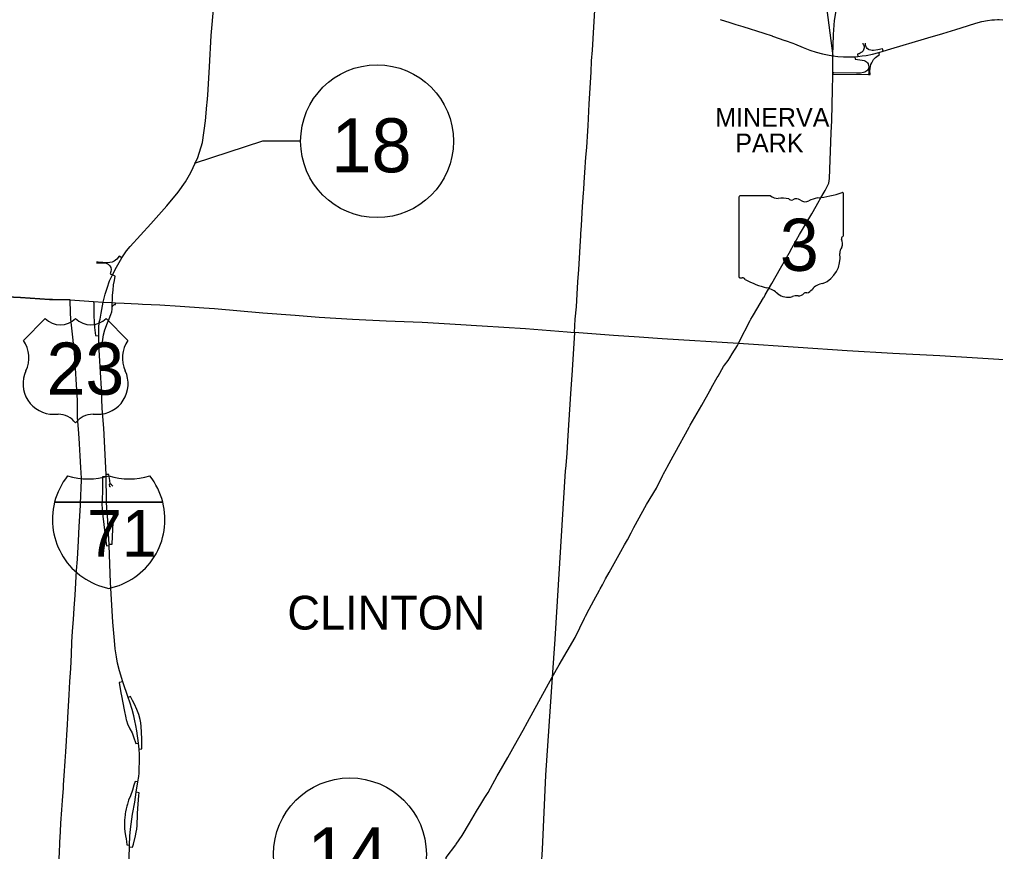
# Model space of a CAD drawing. Extents: x -1146 to -445, y -1283 to -822.
# Drawn here: x -887.8 to -822.8, y -1003.9 to -948.4 of the extents above; entities that cross this region are included whole.
import ezdxf

# ---------------------------------------------------------------- set-up
doc = ezdxf.new("R2010")
doc.units = 0
for name, color, linetype in [('Default', 7, 'Continuous'), ('GM_X_Corporation_Text', 7, 'Continuous'), ('GM_X_Interchange_Ramps', 7, 'Continuous'), ('GM_X_Interstate_Route', 7, 'Continuous'), ('GM_X_Interstate_Shield', 7, 'Continuous'), ('GM_X_State_Route', 7, 'Continuous'), ('GM_X_State_Shield', 7, 'Continuous'), ('GM_X_Township', 7, 'Continuous'), ('GM_X_Township_Text', 7, 'Continuous'), ('GM_X_US_Route', 7, 'Continuous'), ('GM_X_US_Shield', 7, 'Continuous')]:
    doc.layers.add(name, color=color, linetype=linetype)

msp = doc.modelspace()

# ---------------------------------------------------------------- linework, layer by layer
at = {"layer": 'Default'}
for points in [[(-837.735, -938.717), (-835.188, -938.717), (-833.622, -950.863)], [(-869.091, -956.557), (-871.638, -956.557), (-876.187, -958.029)]]:
    msp.add_lwpolyline(points, dxfattribs=at)
for centre in [(-863.997, -956.557), (-865.804, -1004.109)]:
    msp.add_circle(centre, 5.094, dxfattribs=at)
at = {"layer": 'GM_X_Interchange_Ramps'}
for points in [[(-831.618, -950.017), (-831.616, -950.063), (-831.572, -950.114), (-831.55, -950.171), (-831.538, -950.235), (-831.54, -950.318), (-831.552, -950.403), (-831.574, -950.468), (-831.603, -950.523), (-831.635, -950.561), (-831.678, -950.608), (-831.73, -950.646), (-831.792, -950.689), (-831.858, -950.72), (-831.911, -950.737), (-831.963, -950.745), (-831.957, -950.899)], [(-830.252, -950.545), (-830.296, -950.39), (-830.61, -950.45), (-830.905, -950.494), (-830.993, -950.498), (-831.082, -950.49), (-831.19, -950.468), (-831.247, -950.432), (-831.321, -950.379), (-831.377, -950.313), (-831.404, -950.26), (-831.442, -950.15), (-831.444, -950.07), (-831.447, -950.009)], [(-833.626, -952.081), (-833.56, -952.082), (-831.23, -952.113), (-831.139, -952.111), (-831.141, -951.85), (-831.135, -951.701), (-831.116, -951.574), (-831.076, -951.443), (-831.028, -951.323), (-830.956, -951.192), (-830.897, -951.11), (-830.847, -951.045), (-830.773, -950.971), (-830.686, -950.896), (-830.604, -950.83), (-830.513, -950.78), (-830.555, -950.63)], [(-832.141, -950.917), (-832.136, -951.081), (-831.659, -951.152), (-831.539, -951.18), (-831.45, -951.218), (-831.372, -951.266), (-831.31, -951.331), (-831.267, -951.401), (-831.235, -951.494), (-831.229, -951.602), (-831.249, -951.699), (-831.273, -951.745), (-831.306, -951.807), (-831.35, -951.86), (-831.408, -951.908), (-831.493, -951.954), (-831.573, -951.98), (-831.776, -952.01), (-832.033, -952.022), (-833.549, -951.993), (-833.626, -951.992)], [(-831.249, -951.699), (-831.219, -951.703), (-831.224, -952.039), (-831.23, -952.113)], [(-882.701, -964.661), (-882.603, -964.665), (-882.05, -964.693), (-881.909, -964.747), (-881.809, -964.866), (-881.751, -964.978), (-881.728, -965.113), (-881.748, -965.246), (-881.795, -965.395), (-881.637, -965.467)], [(-881.008, -964.337), (-881.174, -964.216), (-881.345, -964.417), (-881.513, -964.548), (-881.66, -964.624), (-881.809, -964.651), (-881.953, -964.659), (-882.592, -964.628), (-882.698, -964.622)], [(-881.653, -967.321), (-881.639, -967.181), (-881.622, -966.827), (-881.595, -966.497), (-881.555, -966.141), (-881.502, -965.842), (-881.442, -965.556), (-881.637, -965.467)], [(-882.885, -967.245), (-882.865, -967.388), (-882.877, -967.789), (-882.88, -968.19), (-882.854, -968.593), (-882.826, -968.967), (-882.764, -969.521), (-882.551, -969.525)], [(-882.532, -970.119), (-882.316, -970.107), (-882.282, -969.778), (-882.226, -969.47), (-882.135, -969.13), (-881.968, -968.668), (-881.856, -968.391), (-881.744, -968.118), (-881.684, -967.935), (-881.657, -967.764), (-881.649, -967.573), (-881.647, -967.406), (-881.653, -967.321)], [(-881.649, -967.573), (-881.632, -967.574), (-881.609, -967.519), (-881.571, -967.485), (-881.534, -967.462), (-881.489, -967.451), (-881.43, -967.444), (-881.434, -967.328)], [(-882.049, -978.937), (-882.299, -978.947), (-882.306, -979.83), (-882.323, -980.501), (-882.331, -980.836), (-882.326, -980.994)], [(-881.615, -979.55), (-881.687, -979.48), (-881.793, -979.412), (-881.816, -979.179), (-881.882, -978.777), (-882.058, -978.784)], [(-881.762, -979.6), (-881.804, -979.599), (-881.819, -979.417), (-881.793, -979.412)], [(-882.326, -980.994), (-882.317, -981.184), (-882.157, -982.494), (-882.055, -983.39), (-882.04, -983.534), (-881.846, -983.522)], [(-881.851, -983.436), (-881.646, -983.423), (-881.598, -982.43), (-881.557, -981.581), (-881.559, -981.349), (-881.588, -981.169)], [(-880.951, -992.614), (-881.178, -992.663), (-881.064, -993.335), (-881.023, -993.549), (-880.845, -994.479), (-880.734, -995.011), (-880.711, -995.134)], [(-879.756, -995.23), (-879.777, -995.114), (-879.878, -994.78), (-880.003, -994.445), (-880.168, -994.09), (-880.286, -993.854), (-880.438, -993.592), (-880.593, -993.645)], [(-880.711, -995.134), (-880.702, -995.189), (-880.629, -995.403), (-880.463, -995.74), (-880.329, -996.006), (-880.224, -996.266), (-880.063, -996.724), (-879.895, -996.698)], [(-879.859, -997.099), (-879.663, -997.078), (-879.681, -996.439), (-879.696, -995.969), (-879.715, -995.58), (-879.748, -995.337), (-879.756, -995.23)], [(-879.93, -999.272), (-880.127, -999.245), (-880.198, -999.49), (-880.302, -999.822), (-880.437, -1000.205), (-880.552, -1000.507), (-880.631, -1000.761), (-880.683, -1000.911), (-880.723, -1001.086), (-880.769, -1001.289), (-880.776, -1001.412)], [(-879.967, -1001.465), (-879.961, -1001.376), (-879.919, -1000.759), (-879.871, -1000.192), (-879.854, -1000.006), (-880.054, -999.967)], [(-880.776, -1001.412), (-880.78, -1001.471), (-880.827, -1001.832), (-880.84, -1002.19), (-880.831, -1002.38), (-880.807, -1002.59), (-880.757, -1002.874), (-880.716, -1003.077), (-880.687, -1003.258), (-880.673, -1003.479), (-880.485, -1003.491)], [(-880.495, -1003.622), (-880.287, -1003.635), (-880.239, -1003.424), (-880.106, -1002.877), (-880.05, -1002.625), (-880.013, -1002.426), (-879.983, -1002.194), (-879.978, -1002.071), (-879.973, -1001.564), (-879.967, -1001.465)]]:
    msp.add_lwpolyline(points, dxfattribs=at)
at = {"layer": 'GM_X_Interstate_Route'}
for points in [[(-875.331, -954.149), (-875.316, -953.973), (-875.274, -953.484), (-875.171, -951.599), (-875.053, -949.514), (-874.883, -947.533), (-874.865, -947.176), (-874.795, -945.801), (-874.743, -945.009), (-874.694, -943.642)], [(-882.251, -967.29), (-882.112, -966.761), (-881.976, -966.347), (-881.821, -965.872), (-881.637, -965.467), (-881.365, -964.947), (-881.008, -964.337), (-880.69, -963.865), (-880.456, -963.572), (-879.063, -962.065), (-877.998, -960.869), (-877.245, -959.951), (-876.759, -959.252), (-876.405, -958.632), (-875.947, -957.632), (-875.64, -956.631), (-875.42, -955.188), (-875.331, -954.149)], [(-882.044, -979.439), (-882.049, -978.937), (-882.058, -978.784), (-882.215, -975.701), (-882.311, -974.382), (-882.372, -973.073), (-882.493, -970.854), (-882.532, -970.119), (-882.551, -969.525), (-882.542, -969.008), (-882.507, -968.619), (-882.446, -968.414), (-882.391, -968.028), (-882.251, -967.29)], [(-882.021, -980.568), (-882.039, -979.966), (-882.044, -979.439)], [(-880.299, -1001.442), (-880.146, -1000.637), (-880.054, -999.967), (-879.93, -999.272), (-879.882, -998.93), (-879.862, -998.691), (-879.845, -998.319), (-879.84, -998.01), (-879.84, -997.458), (-879.859, -997.099), (-879.895, -996.698), (-880.005, -995.886), (-880.068, -995.519), (-880.151, -995.204), (-880.214, -994.869), (-880.324, -994.443), (-880.478, -993.967), (-880.593, -993.645), (-880.951, -992.614), (-881.169, -991.878), (-881.293, -991.371), (-881.37, -990.931), (-881.446, -990.415), (-881.503, -989.861), (-881.616, -988.638), (-881.769, -985.99), (-881.846, -983.522), (-881.851, -983.436), (-881.889, -982.737), (-881.968, -981.498), (-882.007, -981.07), (-882.021, -980.568)], [(-879.879, -1009.865), (-879.984, -1009.605), (-880.067, -1009.321), (-880.181, -1008.881), (-880.277, -1008.369), (-880.32, -1008.021), (-880.35, -1007.755), (-880.418, -1007.065), (-880.473, -1006.36), (-880.538, -1004.983), (-880.495, -1003.622), (-880.485, -1003.491), (-880.468, -1002.89), (-880.436, -1002.425), (-880.299, -1001.442)]]:
    msp.add_lwpolyline(points, dxfattribs=at)
at = {"layer": 'GM_X_Interstate_Shield'}
for p, q in [((-885.489, -980.631), (-878.275, -980.631)), ((-878.275, -980.631), (-885.489, -980.631)), ((-878.275, -980.631), (-885.489, -980.631))]:
    msp.add_line(p, q, dxfattribs=at)
for centre, start, end in [((-880.945, -981.78), 141.66896, 165.80665), ((-883.252, -974.39), 253.00908, 286.99093), ((-880.512, -974.39), 253.00908, 286.99093), ((-882.82, -981.78), 14.19335, 38.33104), ((-880.945, -981.78), 165.80665, 258.46304), ((-882.82, -981.78), 281.53696, 14.19335)]:
    msp.add_arc(centre, 4.688, start, end, dxfattribs=at)
at = {"layer": 'GM_X_State_Route'}
for points in [[(-833.572, -949.535), (-833.567, -949.437), (-833.501, -948.499), (-833.405, -947.866), (-833.225, -946.919), (-832.89, -945.628), (-832.441, -943.953)], [(-841.13, -948.437), (-840.49, -948.636)], [(-840.49, -948.636), (-840.076, -948.764), (-839.608, -948.91), (-838.225, -949.341), (-837.653, -949.535), (-837.643, -949.538), (-836.817, -949.826), (-836.797, -949.833)], [(-825.43, -949.102), (-825.059, -948.991), (-824.094, -948.686), (-823.684, -948.58), (-823.31, -948.5)], [(-823.31, -948.5), (-823.309, -948.5), (-823.009, -948.467), (-822.831, -948.452), (-822.65, -948.447), (-822.534, -948.445), (-822.279, -948.461), (-821.988, -948.471), (-820.958, -948.549), (-819.698, -948.64), (-819.18, -948.693)], [(-833.623, -951.004), (-833.622, -950.863), (-833.6, -950.087), (-833.572, -949.535)], [(-829.757, -950.397), (-827.497, -949.722), (-827.284, -949.658)], [(-827.284, -949.658), (-826.295, -949.361)], [(-826.295, -949.361), (-825.43, -949.102)], [(-836.797, -949.833), (-836.275, -950.015), (-836.168, -950.06)], [(-836.168, -950.06), (-835.594, -950.3), (-835.147, -950.472), (-834.724, -950.617), (-834.295, -950.734), (-833.973, -950.803), (-833.622, -950.863)], [(-833.628, -952.21), (-833.626, -952.081), (-833.626, -951.992), (-833.626, -951.508), (-833.623, -951.004)], [(-833.622, -950.863), (-833.29, -950.902), (-832.903, -950.927), (-832.524, -950.93), (-832.141, -950.917), (-831.957, -950.899), (-831.655, -950.87), (-831.391, -950.828), (-830.978, -950.742), (-830.555, -950.63), (-830.252, -950.545), (-829.757, -950.397)], [(-833.641, -953.107), (-833.628, -952.21)], [(-833.722, -955.998), (-833.69, -955.169), (-833.641, -953.107)], [(-834.474, -960.448), (-834.133, -959.84), (-833.895, -959.351), (-833.838, -959.03), (-833.722, -955.998)], [(-839.074, -968.418), (-838.978, -968.253), (-838.906, -968.132), (-838.233, -966.995), (-838.203, -966.944), (-838.122, -966.804), (-837.684, -966.041), (-837.098, -965.021), (-836.439, -963.864), (-836.429, -963.847), (-835.836, -962.783), (-835.01, -961.404), (-834.518, -960.525), (-834.474, -960.448)], [(-839.855, -969.938), (-839.123, -968.503), (-839.074, -968.418)], [(-840.316, -970.738), (-839.982, -970.169)], [(-839.982, -970.169), (-839.915, -970.055)], [(-839.915, -970.055), (-839.855, -969.938)], [(-840.837, -971.5), (-840.603, -971.18)], [(-840.603, -971.18), (-840.472, -971.002), (-840.316, -970.738)], [(-841.695, -972.985), (-841.318, -972.317), (-841.267, -972.225), (-840.901, -971.587), (-840.837, -971.5)], [(-844.158, -977.353), (-843.204, -975.623), (-843.129, -975.486), (-842.359, -974.163), (-841.811, -973.19), (-841.76, -973.1)], [(-841.76, -973.1), (-841.695, -972.985)], [(-844.536, -978.049), (-844.27, -977.555), (-844.158, -977.353)], [(-844.911, -978.747), (-844.708, -978.37), (-844.661, -978.282)], [(-844.661, -978.282), (-844.536, -978.049)], [(-845.366, -979.699), (-845.366, -979.699), (-844.959, -978.835), (-844.911, -978.747)], [(-847.069, -982.672), (-846.977, -982.501), (-846.875, -982.314), (-846.034, -980.777), (-845.366, -979.699)], [(-848.974, -986.137), (-848.762, -985.743), (-848.529, -985.326), (-847.738, -983.915), (-847.501, -983.474), (-847.314, -983.127), (-847.069, -982.672)], [(-849.161, -986.485), (-849.117, -986.403), (-848.974, -986.137)], [(-849.851, -987.76), (-849.544, -987.193), (-849.161, -986.485)], [(-850.102, -988.224), (-849.851, -987.76)], [(-851.848, -991.485), (-850.794, -989.645), (-850.173, -988.355), (-850.102, -988.224)], [(-853.978, -995.304), (-852.318, -992.307), (-851.848, -991.485)], [(-855.98, -998.882), (-855.848, -998.646), (-855.287, -997.657), (-854.839, -996.865), (-854.265, -995.839), (-853.978, -995.304)], [(-857.069, -1000.758), (-856.807, -1000.329), (-856.592, -999.981), (-855.98, -998.882)], [(-859.422, -1004.861), (-859.421, -1004.844), (-859.407, -1004.65), (-859.393, -1004.464), (-859.383, -1004.328), (-858.751, -1003.47), (-858.724, -1003.426), (-858.321, -1002.852), (-857.837, -1002.03), (-857.36, -1001.235), (-857.069, -1000.758)]]:
    msp.add_lwpolyline(points, dxfattribs=at)
at = {"layer": 'GM_X_State_Shield'}
for p, q in [((-832.913, -962.832), (-832.913, -960.068)), ((-839.874, -960.29), (-839.874, -965.573)), ((-837.767, -960.199), (-839.806, -960.199)), ((-832.914, -962.831), (-832.913, -962.832))]:
    msp.add_line(p, q, dxfattribs=at)
for centre, radius, start, end in [((-835.393, -952.997), 7.382, 275.84447, 288.90645), ((-832.991, -960.057), 0.0775, 351.86209, 97.738), ((-839.794, -960.279), 0.0806, 98.1301, 188.1301), ((-837.282, -959.586), 0.782, 231.61951, 271.11188), ((-837.022, -963.165), 2.808, 80.48669, 94.98827), ((-836.385, -960.252), 0.226, 219.79206, 297.10237), ((-836.054, -960.862), 0.469, 54.46668, 119.14113), ((-835.448, -960.025), 0.564, 233.85621, 294.82819), ((-834.451, -961.813), 1.485, 97.34618, 120.76885), ((-832.931, -963.035), 0.12, 107.94398, 210.33697), ((-833.694, -963.384), 0.72, 340.03296, 23.64957), ((-832.996, -962.843), 0.0829, 289.60381, 7.73413), ((-832.636, -963.989), 0.524, 136.8065, 186.92959), ((-834.979, -964.34), 1.846, 292.30889, 8.98584), ((-839.794, -965.585), 0.0814, 171.95839, 258.30661), ((-839.781, -965.044), 0.621, 267.33899, 280.60386), ((-839.654, -965.878), 0.224, 29.74838, 93.27175), ((-836.828, -961.131), 5.331, 240.41292, 257.1985), ((-838.417, -967.947), 1.668, 47.18416, 75.83597), ((-835.482, -966.085), 0.597, 282.87319, 323.27711), ((-834.201, -967.057), 1.011, 94.40312, 142.57675), ((-836.613, -965.904), 1.058, 230.70037, 286.29184), ((-836.002, -967.731), 0.87, 85.69512, 111.20995), ((-835.925, -966.3), 0.564, 268.77702, 315.54927), ((-835.414, -966.812), 0.159, 65.75173, 132.64842)]:
    msp.add_arc(centre, radius, start, end, dxfattribs=at)
at = {"layer": 'GM_X_Township'}
for points in [[(-821.102, -971.211), (-826.477, -970.87), (-829.611, -970.721), (-832.665, -970.525), (-835.933, -970.306), (-839.915, -970.055), (-844.994, -969.733), (-846.52, -969.629), (-848.226, -969.512), (-850.829, -969.316), (-850.781, -968.414), (-850.711, -967.592), (-850.659, -966.757), (-850.607, -965.924), (-850.556, -965.112), (-850.508, -964.343), (-850.46, -963.567), (-850.414, -962.835), (-850.408, -962.726), (-850.373, -962.175), (-850.294, -960.905), (-850.237, -959.988), (-850.224, -959.784), (-850.194, -959.301), (-850.153, -958.649), (-850.089, -957.614), (-850.013, -956.979), (-849.943, -955.865), (-849.931, -955.522), (-849.852, -954.052), (-849.725, -951.96), (-849.7, -951.195), (-849.646, -950.492), (-849.428, -947.009)], [(-889.657, -966.886), (-887.755, -966.987), (-885.839, -967.112), (-884.443, -967.135), (-882.885, -967.245), (-882.251, -967.29), (-881.653, -967.321), (-881.434, -967.328), (-880.842, -967.363), (-879.909, -967.398), (-879.624, -967.422), (-878.467, -967.473), (-877.122, -967.562), (-875.547, -967.66), (-874.823, -967.713), (-871.598, -967.99), (-869.448, -968.156), (-867.856, -968.289), (-865.629, -968.428), (-863.378, -968.526), (-860.993, -968.627), (-858.422, -968.768), (-857.371, -968.85), (-857.001, -968.868), (-854.097, -969.054), (-851.315, -969.27), (-850.829, -969.316), (-850.991, -971.819), (-851.094, -973.409), (-851.273, -976.17), (-851.349, -977.349), (-851.403, -978.185), (-851.433, -978.387), (-851.457, -978.531), (-852.14, -989.762), (-852.318, -992.307), (-852.774, -998.838), (-852.989, -1003.797), (-853.066, -1004.818)]]:
    msp.add_lwpolyline(points, dxfattribs=at)
at = {"layer": 'GM_X_US_Route'}
for points in [[(-885.635, -967.115), (-885.839, -967.112), (-887.755, -966.987), (-889.657, -966.886), (-891.566, -966.763), (-892.459, -966.706), (-893.437, -966.643), (-894.117, -966.599), (-895.339, -966.52), (-896.065, -966.473), (-897.212, -966.399)], [(-884.443, -967.135), (-885.635, -967.115)], [(-883.697, -979.025), (-883.737, -978.318), (-883.782, -977.534), (-883.828, -976.729), (-883.829, -976.708), (-883.881, -976.041), (-883.967, -974.956), (-883.969, -974.927), (-883.972, -973.817), (-884.032, -972.807), (-884.106, -971.696), (-884.168, -970.666), (-884.266, -969.618), (-884.362, -968.816), (-884.407, -968.413), (-884.437, -968.006), (-884.443, -967.135)], [(-883.771, -980.848), (-883.764, -980.705), (-883.69, -979.157), (-883.697, -979.026), (-883.697, -979.025)], [(-884.511, -993.471), (-884.466, -992.575), (-884.417, -991.728), (-884.372, -990.776), (-884.337, -989.964), (-884.284, -989.219), (-884.23, -988.458), (-884.18, -987.696), (-884.123, -986.834), (-884.069, -985.999), (-884.019, -985.193), (-883.971, -984.421), (-883.896, -983.213), (-883.845, -982.246), (-883.771, -980.848)], [(-885.259, -1005.328), (-885.234, -1004.896), (-885.156, -1004.04), (-885.15, -1003.32), (-885.098, -1002.6), (-885.063, -1002.025), (-885.014, -1001.146), (-884.956, -1000.532), (-884.903, -999.705), (-884.888, -999.47), (-884.85, -998.876), (-884.788, -997.901), (-884.748, -997.271), (-884.702, -996.553), (-884.677, -996.149), (-884.634, -995.472), (-884.605, -994.976), (-884.511, -993.471)]]:
    msp.add_lwpolyline(points, dxfattribs=at)
at = {"layer": 'GM_X_US_Shield'}
for p, q in [((-886.118, -968.384), (-887.568, -969.834)), ((-880.607, -969.834), (-882.057, -968.384)), ((-885.538, -974.765), (-885.248, -974.765)), ((-882.928, -974.765), (-882.638, -974.765))]:
    msp.add_line(p, q, dxfattribs=at)
for centre, radius, start, end in [((-885.103, -967.348), 1.45, 225.573, 314.427), ((-883.073, -967.348), 1.45, 225.573, 314.427), ((-889.231, -970.999), 2.03, 334.54712, 35.00093), ((-878.944, -970.999), 2.03, 144.99907, 205.45288), ((-885.561, -972.735), 2.03, 154.83192, 270.63826), ((-882.615, -972.735), 2.03, 269.36174, 25.16808), ((-885.248, -976.215), 1.45, 36.8699, 90), ((-882.928, -976.215), 1.45, 90, 143.1301)]:
    msp.add_arc(centre, radius, start, end, dxfattribs=at)

# ---------------------------------------------------------------- texts
at = {"layer": 'Default'}
for s, p in [('18', (-867.047, -958.627)), ('14', (-868.63, -1005.909))]:
    msp.add_text(s, height=3.6, dxfattribs=at).set_placement(p)
at = {"layer": 'GM_X_Corporation_Text'}
for s, p in [('MINERVA', (-841.458, -955.59)), ('PARK', (-840.122, -957.296))]:
    msp.add_text(s, height=1.25, rotation=0.00001, dxfattribs=at).set_placement(p)
at = {"layer": 'GM_X_Interstate_Shield'}
msp.add_text('71', height=3.125, dxfattribs=at).set_placement((-883.326, -984.264))
at = {"layer": 'GM_X_State_Shield'}
msp.add_text('3', height=3.48, dxfattribs=at).set_placement((-837.145, -965.201))
at = {"layer": 'GM_X_Township_Text'}
msp.add_text('CLINTON', height=2.25, rotation=0.00001, dxfattribs=at).set_placement((-869.974, -989.121))
at = {"layer": 'GM_X_US_Shield'}
msp.add_text('23', height=3.4805, dxfattribs=at).set_placement((-886.025, -973.46))

doc.saveas('drawing.dxf')
